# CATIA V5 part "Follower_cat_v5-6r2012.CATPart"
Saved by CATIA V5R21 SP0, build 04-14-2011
Part number: Follower
Bounding box of the stored display mesh (mm): x -9.942 to 9.942, y -9.942 to 9.942, z 0 to 100
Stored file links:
  D:\CATIA V5R21 E-RESOURCES\CATIA-V5R21\catia-v5r21-Tut\c16-catia-v5r21-tut\c16-catia-v5r21-tut03\Follower_cat_v5r21.CATPart
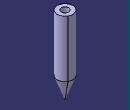
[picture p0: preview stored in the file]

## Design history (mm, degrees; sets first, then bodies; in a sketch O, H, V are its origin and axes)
Body1 (main body)
  Sketch1 on yz-plane, origin (0, 0, 0), H (0, 1, 0), V (0, 0, 1)
    line L1 (0, 0) -> (10, 27.4748)
    point P1 (10, 27.4748)
    line L2 (10, 27.4748) -> (10, 100)
    point P2 (10, 27.4748)
    point P3 (10, 100)
    point P4 (0, 100)
    point P5 (10, 91.3901)
    line L3 (0, 0) -> (0, 100)
    reference intersected line E1 through (0, 0) direction (-1, 0) from xy-plane
    reference intersected line E3 through (0, 0) direction (0, 1) from zx-plane
    line L4 (0, 100) -> (10, 100)
    point P6 (10, 100)
    angle L1 L3 = 20
    distance O P4 = 100
    length L4 = 10
    coincidence: P2 L1, P4 V, P5 L2, P2 P1, E3 P4, P1 L2, P6 L2, P6 P3
    vertical: L2 V, L3 V, E3 V
    horizontal: E1 H, L4 H
    perpendicularity: E1 L2
  Shaft1: profile Sketch1, axis Sketch1.L3, angle 360
  Sketch2 on face of Shaft1 from Sketch1.L4, origin (0, 0, 100), H (1, 0, 0), V (0, 1, 0)
    point P1 (0, 0)
  Hole1: placed by Sketch2, at (0, 0, 100) direction (0, 0, -1), diameter 10, depth 55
